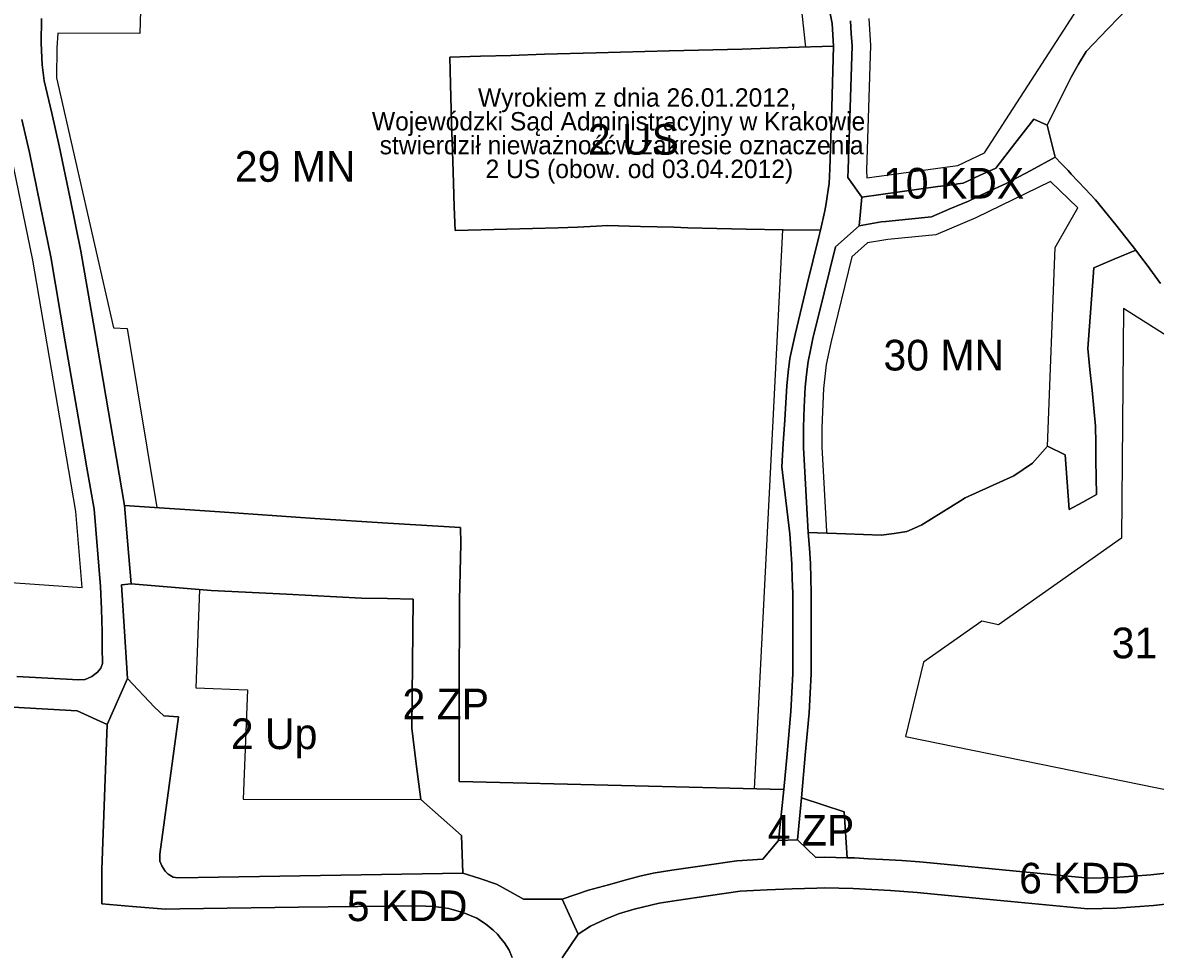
# Model space of a CAD drawing. Extents: x 7423432 to 7425824, y 5537848 to 5539677.
# Drawn here: x 7424841.5 to 7425211.1, y 5538909.6 to 5539212.8 of the extents above; entities that cross this region are included whole.
import ezdxf

# ---------------------------------------------------------------- set-up
doc = ezdxf.new("R2010")
doc.units = 0
for name, color, linetype in [('linie_rozgraniczajace', 7, 'Continuous'), ('linie_zabudowy_nieprzekraczalne', 7, 'Continuous'), ('oznaczenia_przeznaczen', 7, 'Continuous')]:
    doc.layers.add(name, color=color, linetype=linetype)

msp = doc.modelspace()

# ---------------------------------------------------------------- linework, layer by layer
at = {"layer": 'linie_rozgraniczajace'}
for points in [[(7425202.79, 5539218.2), (7425195.64, 5539210.8), (7425188.5, 5539203.4), (7425186.07, 5539199.23), (7425183.64, 5539195.05), (7425180.6, 5539188.95), (7425177.55, 5539182.84), (7425175.8, 5539179.33), (7425171.41, 5539181.36), (7425165.21, 5539173.37), (7425159.01, 5539165.39), (7425153.7, 5539162.91), (7425148.39, 5539160.43), (7425146.67, 5539160.2), (7425144.94, 5539159.96), (7425140.17, 5539159.31), (7425127.74, 5539157.6), (7425115.3, 5539155.9), (7425110.75, 5539162.29), (7425110.89, 5539164.91), (7425111.51, 5539185.06), (7425112.12, 5539205.22), (7425111.86, 5539209.3), (7425111.6, 5539213.38)], [(7425175.8, 5539179.33), (7425177.55, 5539182.84), (7425180.6, 5539188.95), (7425183.64, 5539195.05), (7425186.07, 5539199.23), (7425188.5, 5539203.4), (7425195.64, 5539210.8), (7425202.79, 5539218.2)], [(7424847.63, 5539214.18), (7424847.51, 5539206.17), (7424847.89, 5539199.1), (7424848.52, 5539193.86), (7424850.98, 5539183.26), (7424853.44, 5539172.66), (7424856.97, 5539155.46), (7424860.5, 5539138.26), (7424865, 5539112.05), (7424869.51, 5539085.84), (7424872.12, 5539070.59), (7424874.73, 5539055.33), (7424875.81, 5539042.52), (7424876.89, 5539029.71), (7424873.71, 5539029.45), (7424874.72, 5539014.17), (7424875.72, 5538998.89), (7424869.07, 5538983.86), (7424859.26, 5538988.38), (7424845.95, 5538989.12), (7424832.64, 5538989.85)], [(7424847.51, 5539206.17), (7424847.63, 5539214.18)], [(7425104.97, 5539215.75), (7425105.64, 5539212.56), (7425106.12, 5539205.12), (7425091.22, 5539204.65), (7425076.32, 5539204.19), (7425052.48, 5539203.6), (7425028.65, 5539203.01), (7425011.78, 5539202.49), (7425000.83, 5539202.1), (7424990.84, 5539201.84), (7424980.84, 5539201.58), (7424980.97, 5539197.17), (7424981.1, 5539192.76), (7424981.46, 5539180.22), (7424981.82, 5539167.67), (7424982.07, 5539160.46), (7424982.34, 5539152.74), (7424982.61, 5539145.02), (7424999.43, 5539145.44), (7425016.25, 5539145.86)], [(7425098.64, 5539031.61), (7425098.75, 5539026.79), (7425098.79, 5539013.6), (7425098.82, 5539000.41), (7425098.48, 5538994.05), (7425098.14, 5538987.69), (7425096.88, 5538973.84), (7425095.61, 5538959.99), (7425094.98, 5538953.12), (7425094.35, 5538946.25), (7425088.17, 5538946.02), (7425089.83, 5538962.65), (7425090.9, 5538974.33), (7425092.16, 5538988.13), (7425092.49, 5538994.35), (7425092.82, 5539000.56), (7425092.79, 5539013.64), (7425092.75, 5539026.71), (7425092.64, 5539031.44), (7425092.53, 5539036.16), (7425092.19, 5539041.13), (7425091.86, 5539046.09), (7425090.52, 5539056.98), (7425089.17, 5539067.87), (7425089.65, 5539075.54), (7425090.14, 5539083.22), (7425090.47, 5539088.78), (7425090.81, 5539094.35), (7425091.33, 5539098.8), (7425091.86, 5539103.26), (7425092.69, 5539107.18), (7425093.52, 5539111.09), (7425097.42, 5539127.04), (7425101.33, 5539142.99), (7425101.8, 5539145.1), (7425103.23, 5539151.45), (7425103.64, 5539153.79), (7425104.05, 5539156.13), (7425104.35, 5539158.26), (7425104.65, 5539160.39), (7425104.89, 5539165.16), (7425105.51, 5539185.14), (7425106.12, 5539205.12), (7425105.64, 5539212.56), (7425104.97, 5539215.75)], [(7425111.6, 5539213.38), (7425111.86, 5539209.3), (7425112.12, 5539205.22), (7425111.51, 5539185.06), (7425110.89, 5539164.91), (7425110.75, 5539162.29), (7425115.3, 5539155.9), (7425114.47, 5539146.57), (7425106.69, 5539139.66), (7425103.03, 5539124.71), (7425099.37, 5539109.76), (7425098.58, 5539106.02), (7425097.78, 5539102.28), (7425097.29, 5539098.08), (7425096.8, 5539093.89), (7425096.55, 5539087.39), (7425096.31, 5539080.9), (7425096.31, 5539077.58), (7425096.31, 5539074.25), (7425097.08, 5539060.35), (7425097.85, 5539046.45), (7425098.19, 5539041.44), (7425098.52, 5539036.44), (7425098.64, 5539031.61)], [(7425016.25, 5539145.86), (7425022.51, 5539146.15), (7425028.76, 5539146.45), (7425032.29, 5539146.61), (7425043.12, 5539146.33), (7425053.95, 5539146.05), (7425058.51, 5539145.93), (7425068.05, 5539145.67), (7425077.58, 5539145.41), (7425089.69, 5539145.25), (7425101.8, 5539145.1), (7425101.33, 5539142.99), (7425097.42, 5539127.04), (7425093.52, 5539111.09), (7425092.69, 5539107.18), (7425091.86, 5539103.26), (7425091.33, 5539098.8), (7425090.81, 5539094.35), (7425090.47, 5539088.78), (7425090.14, 5539083.22), (7425089.65, 5539075.54), (7425089.17, 5539067.87), (7425090.52, 5539056.98), (7425091.86, 5539046.09), (7425092.19, 5539041.13), (7425092.53, 5539036.16), (7425092.64, 5539031.44), (7425092.75, 5539026.71), (7425092.79, 5539013.64), (7425092.82, 5539000.56), (7425092.49, 5538994.35), (7425092.16, 5538988.13), (7425090.9, 5538974.33), (7425089.83, 5538962.65), (7424983.95, 5538965.33), (7424983.92, 5538992.94), (7424984.07, 5539024.43), (7424984.27, 5539033.7), (7424984.47, 5539042.96), (7424984.4, 5539048.1), (7424960.63, 5539049.59), (7424936.86, 5539051.07), (7424905.8, 5539053.2), (7424874.73, 5539055.33), (7424872.12, 5539070.59), (7424869.51, 5539085.84), (7424865, 5539112.05), (7424860.5, 5539138.26), (7424856.97, 5539155.46), (7424853.44, 5539172.66), (7424850.98, 5539183.26), (7424848.52, 5539193.86), (7424847.89, 5539199.1), (7424847.51, 5539206.17)], [(7424841.18, 5539181.26), (7424843.69, 5539170.4), (7424847.18, 5539153.4), (7424850.67, 5539136.4), (7424855.42, 5539108.74), (7424860.18, 5539081.08), (7424862.49, 5539067.57), (7424864.8, 5539054.06), (7424866.93, 5539028.87), (7424867.17, 5539021.46), (7424867.41, 5539014.06), (7424867.45, 5539008.94), (7424867.5, 5539003.82), (7424866.96, 5539002.21), (7424865.93, 5539000.92), (7424864.03, 5538999.49), (7424861.92, 5538998.6), (7424859.84, 5538998.47), (7424849.72, 5538998.98), (7424839.61, 5538999.48)], [(7424839.61, 5538999.48), (7424849.72, 5538998.98), (7424859.84, 5538998.47), (7424861.92, 5538998.6), (7424864.03, 5538999.49), (7424865.93, 5539000.92), (7424866.96, 5539002.21), (7424867.5, 5539003.82), (7424867.45, 5539008.94), (7424867.41, 5539014.06), (7424867.17, 5539021.46), (7424866.93, 5539028.87), (7424864.8, 5539054.06), (7424862.49, 5539067.57), (7424860.18, 5539081.08), (7424855.42, 5539108.74), (7424850.67, 5539136.4), (7424847.18, 5539153.4), (7424843.69, 5539170.4), (7424841.18, 5539181.26)], [(7425212.82, 5539127.69), (7425208.39, 5539133.68), (7425206.58, 5539136.13), (7425204.77, 5539138.58), (7425198.16, 5539146.81), (7425191.56, 5539155.03), (7425188.14, 5539158.64), (7425183.66, 5539163.41), (7425182.6, 5539164.56), (7425180.5, 5539166.75), (7425178.42, 5539168.91), (7425175.8, 5539179.33)], [(7425235.92, 5538937.77), (7425209.58, 5538934.8), (7425203.8, 5538934.39), (7425198.02, 5538933.98), (7425189.36, 5538933.76), (7425164.61, 5538936.14), (7425139.86, 5538938.53), (7425134.14, 5538939.03), (7425128.42, 5538939.52), (7425122.19, 5538939.84), (7425117.54, 5538940.11), (7425112.89, 5538940.38), (7425110.5, 5538940.43), (7425109.53, 5538955.37), (7425095.61, 5538959.99), (7425096.88, 5538973.84), (7425098.14, 5538987.69), (7425098.48, 5538994.05), (7425098.82, 5539000.41), (7425098.79, 5539013.6), (7425098.75, 5539026.79), (7425098.64, 5539031.61), (7425098.52, 5539036.44), (7425098.19, 5539041.44), (7425097.85, 5539046.45), (7425110.11, 5539046.03), (7425121.67, 5539045.62), (7425125.84, 5539046.2), (7425130, 5539046.78), (7425132.46, 5539047.91), (7425134.92, 5539049.04), (7425141.19, 5539052.91), (7425147.47, 5539056.78), (7425149.07, 5539057.76), (7425156.98, 5539061.39), (7425164.88, 5539065.02), (7425167.97, 5539067.09), (7425171.06, 5539069.17), (7425175.85, 5539074.68), (7425181.67, 5539071.86), (7425182.34, 5539062.92), (7425183.01, 5539053.98), (7425187.44, 5539056.43), (7425191.86, 5539058.87), (7425191.79, 5539064.46), (7425191.72, 5539070.06), (7425191.65, 5539075.65), (7425191.58, 5539081.24), (7425191.04, 5539087.08), (7425190.49, 5539092.91), (7425189.76, 5539099.7), (7425189.03, 5539106.49), (7425190.02, 5539119.67), (7425191.02, 5539132.86), (7425197.89, 5539135.72), (7425204.77, 5539138.58), (7425206.58, 5539136.13), (7425208.39, 5539133.68), (7425212.82, 5539127.69)], [(7425001.27, 5538907.91), (7425000.25, 5538910.22), (7424998.73, 5538912.71), (7424997.56, 5538914.1), (7424996.4, 5538915.49), (7424995.04, 5538916.82), (7424993.75, 5538917.86), (7424992.47, 5538918.9), (7424989.67, 5538920.65), (7424985.48, 5538922.45), (7424980.61, 5538923.84), (7424975.67, 5538924.53), (7424973, 5538924.63), (7424970.2, 5538924.74), (7424931.51, 5538924.27), (7424892.83, 5538923.8), (7424888.07, 5538923.6), (7424877.35, 5538924.46), (7424867.31, 5538925.4), (7424867.36, 5538936.6), (7424868.21, 5538960.23), (7424869.07, 5538983.86), (7424875.72, 5538998.89), (7424884.51, 5538989.53), (7424887.57, 5538986.72), (7424892.37, 5538986.4), (7424889.32, 5538963.99), (7424886.26, 5538941.59), (7424886.27, 5538940.44), (7424886.28, 5538939.29), (7424886.91, 5538937.74), (7424887.98, 5538936.03), (7424888.96, 5538935.11), (7424890.57, 5538934.08), (7424892.16, 5538933.84), (7424938.65, 5538934.63), (7424985.14, 5538935.42), (7424990.63, 5538933.62), (7424996.12, 5538931.83), (7425000.5, 5538929.38), (7425004.89, 5538926.94), (7425011.23, 5538926.93), (7425017.56, 5538926.91), (7425022.77, 5538915.5), (7425017.57, 5538907.76)], [(7424832.64, 5538989.85), (7424845.95, 5538989.12), (7424859.26, 5538988.38), (7424869.07, 5538983.86), (7424868.21, 5538960.23), (7424867.36, 5538936.6), (7424867.31, 5538925.4), (7424877.35, 5538924.46), (7424888.07, 5538923.6), (7424892.83, 5538923.8), (7424931.51, 5538924.27), (7424970.2, 5538924.74), (7424973, 5538924.63), (7424975.67, 5538924.53), (7424980.61, 5538923.84), (7424985.48, 5538922.45), (7424989.67, 5538920.65), (7424992.47, 5538918.9), (7424993.75, 5538917.86), (7424995.04, 5538916.82), (7424996.4, 5538915.49), (7424997.56, 5538914.1), (7424998.73, 5538912.71), (7425000.25, 5538910.22), (7425001.27, 5538907.91)], [(7425241.35, 5538928.32), (7425210.49, 5538924.84), (7425204.5, 5538924.41), (7425198.5, 5538923.99), (7425193.76, 5538923.87), (7425189.01, 5538923.75), (7425163.98, 5538926.16), (7425138.95, 5538928.57), (7425133.34, 5538929.06), (7425129, 5538929.38), (7425124.65, 5538929.7), (7425118.59, 5538930.05), (7425112.52, 5538930.39), (7425107.86, 5538930.47), (7425103.2, 5538930.56), (7425100.62, 5538930.46), (7425092.54, 5538930.22), (7425084.47, 5538929.98), (7425080.02, 5538929.73), (7425075.58, 5538929.47), (7425065.2, 5538928), (7425054.83, 5538926.52), (7425049.24, 5538925.62), (7425041.04, 5538923.61), (7425035.93, 5538922.1), (7425031.63, 5538920.4), (7425026.82, 5538918.12), (7425022.77, 5538915.5), (7425017.56, 5538926.91), (7425026.09, 5538929.89), (7425029.38, 5538930.73), (7425032.67, 5538931.56), (7425038.43, 5538933.26), (7425042.84, 5538934.35), (7425047.25, 5538935.43), (7425053.34, 5538936.41), (7425063.96, 5538937.92), (7425074.58, 5538939.43), (7425083.01, 5538939.94), (7425088.17, 5538946.02), (7425094.35, 5538946.25), (7425100.29, 5538940.46), (7425103.11, 5538940.56), (7425110.5, 5538940.43), (7425112.89, 5538940.38), (7425117.54, 5538940.11), (7425122.19, 5538939.84), (7425128.42, 5538939.52), (7425134.14, 5538939.03), (7425139.86, 5538938.53), (7425164.61, 5538936.14), (7425189.36, 5538933.76), (7425198.02, 5538933.98), (7425203.8, 5538934.39), (7425209.58, 5538934.8), (7425235.92, 5538937.77)], [(7425017.57, 5538907.76), (7425022.77, 5538915.5), (7425026.82, 5538918.12), (7425031.63, 5538920.4), (7425035.93, 5538922.1), (7425041.04, 5538923.61), (7425049.24, 5538925.62), (7425054.83, 5538926.52), (7425065.2, 5538928), (7425075.58, 5538929.47), (7425080.02, 5538929.73), (7425084.47, 5538929.98), (7425092.54, 5538930.22), (7425100.62, 5538930.46), (7425103.2, 5538930.56), (7425107.86, 5538930.47), (7425112.52, 5538930.39), (7425118.59, 5538930.05), (7425124.65, 5538929.7), (7425129, 5538929.38), (7425133.34, 5538929.06), (7425138.95, 5538928.57), (7425163.98, 5538926.16), (7425189.01, 5538923.75), (7425193.76, 5538923.87), (7425198.5, 5538923.99), (7425204.5, 5538924.41), (7425210.49, 5538924.84), (7425241.35, 5538928.32)]]:
    msp.add_lwpolyline(points, dxfattribs=at)
for points in [[(7424982.61, 5539145.02), (7424982.34, 5539152.74), (7424982.07, 5539160.46), (7424981.82, 5539167.67), (7424981.46, 5539180.22), (7424981.1, 5539192.76), (7424980.97, 5539197.17), (7424980.84, 5539201.58), (7424990.84, 5539201.84), (7425000.83, 5539202.1), (7425011.78, 5539202.49), (7425028.65, 5539203.01), (7425052.48, 5539203.6), (7425076.32, 5539204.19), (7425091.22, 5539204.65), (7425106.12, 5539205.12), (7425105.51, 5539185.14), (7425104.89, 5539165.16), (7425104.65, 5539160.39), (7425104.35, 5539158.26), (7425104.05, 5539156.13), (7425103.64, 5539153.79), (7425103.23, 5539151.45), (7425101.8, 5539145.1), (7425089.69, 5539145.25), (7425077.58, 5539145.41), (7425068.05, 5539145.67), (7425058.51, 5539145.93), (7425053.95, 5539146.05), (7425043.12, 5539146.33), (7425032.29, 5539146.61), (7425028.76, 5539146.45), (7425022.51, 5539146.15), (7425016.25, 5539145.86), (7424999.43, 5539145.44)], [(7425114.47, 5539146.57), (7425115.3, 5539155.9), (7425127.74, 5539157.6), (7425140.17, 5539159.31), (7425144.94, 5539159.96), (7425146.67, 5539160.2), (7425148.39, 5539160.43), (7425153.7, 5539162.91), (7425159.01, 5539165.39), (7425165.21, 5539173.37), (7425171.41, 5539181.36), (7425175.8, 5539179.33), (7425178.42, 5539168.91), (7425170.41, 5539164.63), (7425162.41, 5539160.35), (7425156.26, 5539157.48), (7425150.1, 5539154.61), (7425144.05, 5539152.06), (7425138, 5539149.5), (7425130.58, 5539148.75), (7425123.15, 5539148), (7425121.68, 5539147.85), (7425118.07, 5539147.21)], [(7425096.31, 5539074.25), (7425096.31, 5539077.58), (7425096.31, 5539080.9), (7425096.55, 5539087.39), (7425096.8, 5539093.89), (7425097.29, 5539098.08), (7425097.78, 5539102.28), (7425098.58, 5539106.02), (7425099.37, 5539109.76), (7425103.03, 5539124.71), (7425106.69, 5539139.66), (7425114.47, 5539146.57), (7425118.07, 5539147.21), (7425121.68, 5539147.85), (7425123.15, 5539148), (7425130.58, 5539148.75), (7425138, 5539149.5), (7425144.05, 5539152.06), (7425150.1, 5539154.61), (7425156.26, 5539157.48), (7425162.41, 5539160.35), (7425170.41, 5539164.63), (7425178.42, 5539168.91), (7425180.5, 5539166.75), (7425182.6, 5539164.56), (7425183.66, 5539163.41), (7425188.14, 5539158.64), (7425191.56, 5539155.03), (7425198.16, 5539146.81), (7425204.77, 5539138.58), (7425197.89, 5539135.72), (7425191.02, 5539132.86), (7425190.02, 5539119.67), (7425189.03, 5539106.49), (7425189.76, 5539099.7), (7425190.49, 5539092.91), (7425191.04, 5539087.08), (7425191.58, 5539081.24), (7425191.65, 5539075.65), (7425191.72, 5539070.06), (7425191.79, 5539064.46), (7425191.86, 5539058.87), (7425187.44, 5539056.43), (7425183.01, 5539053.98), (7425182.34, 5539062.92), (7425181.67, 5539071.86), (7425175.85, 5539074.68), (7425171.06, 5539069.17), (7425167.97, 5539067.09), (7425164.88, 5539065.02), (7425156.98, 5539061.39), (7425149.07, 5539057.76), (7425147.47, 5539056.78), (7425141.19, 5539052.91), (7425134.92, 5539049.04), (7425132.46, 5539047.91), (7425130, 5539046.78), (7425125.84, 5539046.2), (7425121.67, 5539045.62), (7425110.11, 5539046.03), (7425097.85, 5539046.45), (7425097.08, 5539060.35)], [(7424874.73, 5539055.33), (7424905.8, 5539053.2), (7424936.86, 5539051.07), (7424960.63, 5539049.59), (7424984.4, 5539048.1), (7424984.47, 5539042.96), (7424984.27, 5539033.7), (7424984.07, 5539024.43), (7424983.92, 5538992.94), (7424983.95, 5538965.33), (7425089.83, 5538962.65), (7425088.17, 5538946.02), (7425083.01, 5538939.94), (7425074.58, 5538939.43), (7425063.96, 5538937.92), (7425053.34, 5538936.41), (7425047.25, 5538935.43), (7425042.84, 5538934.35), (7425038.43, 5538933.26), (7425032.67, 5538931.56), (7425029.38, 5538930.73), (7425026.09, 5538929.89), (7425017.56, 5538926.91), (7425011.23, 5538926.93), (7425004.89, 5538926.94), (7425000.5, 5538929.38), (7424996.12, 5538931.83), (7424990.63, 5538933.62), (7424985.14, 5538935.42), (7424984.69, 5538947.69), (7424971.43, 5538959.44), (7424969.94, 5538971.07), (7424968.45, 5538982.71), (7424968.68, 5539003.73), (7424968.9, 5539024.76), (7424960.51, 5539024.94), (7424952.11, 5539025.12), (7424927.56, 5539026.35), (7424903.02, 5539027.59), (7424889.96, 5539028.65), (7424876.89, 5539029.71), (7424875.81, 5539042.52)], [(7424873.71, 5539029.45), (7424876.89, 5539029.71), (7424889.96, 5539028.65), (7424903.02, 5539027.59), (7424927.56, 5539026.35), (7424952.11, 5539025.12), (7424960.51, 5539024.94), (7424968.9, 5539024.76), (7424968.68, 5539003.73), (7424968.45, 5538982.71), (7424969.94, 5538971.07), (7424971.43, 5538959.44), (7424984.69, 5538947.69), (7424985.14, 5538935.42), (7424938.65, 5538934.63), (7424892.16, 5538933.84), (7424890.57, 5538934.08), (7424888.96, 5538935.11), (7424887.98, 5538936.03), (7424886.91, 5538937.74), (7424886.28, 5538939.29), (7424886.27, 5538940.44), (7424886.26, 5538941.59), (7424889.32, 5538963.99), (7424892.37, 5538986.4), (7424887.57, 5538986.72), (7424884.51, 5538989.53), (7424875.72, 5538998.89), (7424874.72, 5539014.17)], [(7425094.35, 5538946.25), (7425094.98, 5538953.12), (7425095.61, 5538959.99), (7425109.53, 5538955.37), (7425110.5, 5538940.43), (7425103.11, 5538940.56), (7425100.29, 5538940.46)]]:
    msp.add_lwpolyline(points, close=True, dxfattribs=at)
at = {"layer": 'linie_zabudowy_nieprzekraczalne'}
for points in [[(7425097.01, 5539204.83), (7425094.17, 5539230.89), (7425088.75, 5539245.68), (7425080.4, 5539270.45), (7425056.42, 5539340.26)], [(7424886.5, 5539324.7), (7424898.72, 5539323.98), (7424897.06, 5539264.69), (7424881.4, 5539264.94), (7424879.69, 5539209.32), (7424853.01, 5539209.34), (7424852.7, 5539204.59), (7424852.5, 5539194.84), (7424852.5, 5539194.84), (7424852.5, 5539194.84), (7424871.09, 5539113.28), (7424875.6, 5539113.07), (7424885.23, 5539054.61)], [(7425117.56, 5539214.19), (7425118.13, 5539205.31), (7425116.88, 5539164.67), (7425116.9, 5539162.17), (7425139.36, 5539165.25), (7425144.13, 5539165.9), (7425146.67, 5539166.25), (7425155.38, 5539170.32), (7425155.38, 5539170.32), (7425155.38, 5539170.32), (7425188.24, 5539221.23)], [(7424811.07, 5539032.07), (7424860.94, 5539028.52), (7424858.85, 5539053.3), (7424854.27, 5539080.06), (7424844.77, 5539135.29), (7424837.83, 5539169.12)], [(7425175.85, 5539074.68), (7425178.35, 5539139.45), (7425185.81, 5539152.41), (7425176.86, 5539161.03), (7425152.54, 5539149.13), (7425139.51, 5539143.62), (7425123.76, 5539142.03), (7425122.5, 5539141.9), (7425117.19, 5539140.96), (7425112.07, 5539136.42), (7425105.22, 5539108.42), (7425103.71, 5539101.31), (7425102.78, 5539093.42), (7425102.31, 5539080.79), (7425102.31, 5539074.42), (7425103.84, 5539046.82), (7425103.88, 5539046.25)], [(7425080.29, 5538962.89), (7425089.57, 5539145.26)], [(7425221.12, 5539106.58), (7425200.75, 5539119.54), (7425200.01, 5539044.67), (7425159.92, 5539016.36), (7425154.47, 5539017.61), (7425135.44, 5539004.21), (7425129.52, 5538980.01)], [(7424899.2, 5539027.9), (7424897.96, 5538995.86), (7424914.81, 5538995.21), (7424913.43, 5538959.51), (7424971.43, 5538959.44)], [(7425129.52, 5538980.01), (7425271.97, 5538950.91)]]:
    msp.add_lwpolyline(points, dxfattribs=at)

# ---------------------------------------------------------------- texts
at = {"layer": 'oznaczenia_przeznaczen'}
for s, height, p in [('Wyrokiem z dnia 26.01.2012, ', 6, (7424990.07, 5539185.4)), ('Wojewódzki Sąd Administracyjny w Krakowie ', 6, (7424955.46, 5539177.64)), ('2 US', 10, (7425025.92, 5539169.73)), ('stwierdził nieważnośćw zakresie oznaczenia ', 6, (7424958, 5539169.87)), ('29 MN', 10, (7424910.71, 5539160.9)), ('2 US (obow. od 03.04.2012)', 6, (7424992.55, 5539162.11)), ('10 KDX', 10, (7425122.21, 5539155.43)), ('30 MN', 10, (7425122.37, 5539099.35)), ('31 MN', 10, (7425196.84, 5539005.48)), ('2 ZP', 10, (7424965.43, 5538985.57)), ('2 Up', 10, (7424909.42, 5538975.85)), ('4 ZP', 10, (7425084.6, 5538944.39)), ('6 KDD', 10, (7425166.64, 5538928.76)), ('5 KDD', 10, (7424947.25, 5538919.74))]:
    msp.add_text(s, height=height, dxfattribs=at).set_placement(p)

doc.saveas('drawing.dxf')
